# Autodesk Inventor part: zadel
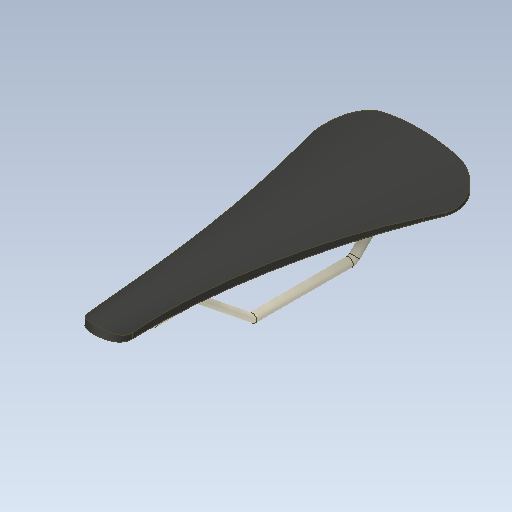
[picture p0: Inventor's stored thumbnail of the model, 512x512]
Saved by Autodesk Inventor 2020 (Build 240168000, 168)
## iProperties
Created: 2017-11
Part Number: zadel
Material: Żywica epoksydowa
Document SubType Name: Modeling
Designer: Tomasz
Density: 1.14 g/cm^3
Appearance: Przezroczysty — szaroniebieski
Author: Tomasz
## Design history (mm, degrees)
feature "Solid1"
node "Bryła1"
